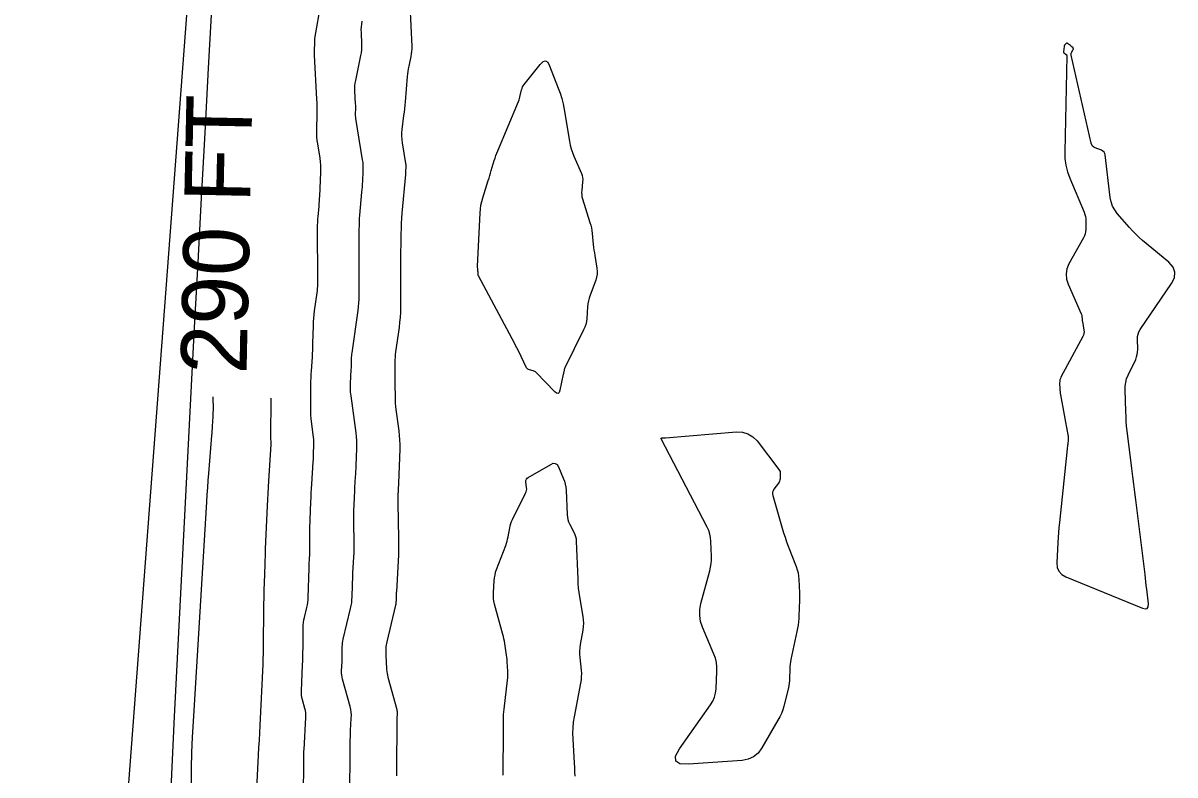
# Model space of a CAD drawing. Extents: x 1768942 to 1774819, y 723037 to 732099.
# Drawn here: x 1770524.3 to 1770629.2, y 730312.3 to 730380.8 of the extents above; entities that cross this region are included whole.
import ezdxf

# ---------------------------------------------------------------- set-up
doc = ezdxf.new("R2010")
doc.units = 0
for name, color, linetype in [('R_Contour Annot', 7, 'Continuous'), ('R_Contours', 7, 'Continuous'), ('R_Horz Alg', 7, 'Continuous')]:
    doc.layers.add(name, color=color, linetype=linetype)

msp = doc.modelspace()

# ---------------------------------------------------------------- linework, layer by layer
at = {"layer": 'R_Contours'}
for points in [[(1770549.81, 730309.86), (1770549.86, 730312.64), (1770549.86, 730312.8), (1770549.87, 730312.97), (1770549.87, 730313.14), (1770549.87, 730313.3), (1770549.87, 730313.97), (1770549.87, 730314.13), (1770549.88, 730314.3), (1770549.88, 730314.46), (1770549.89, 730314.63), (1770550.05, 730317.54), (1770550.05, 730317.75), (1770550.04, 730317.96), (1770550.01, 730318.16), (1770549.96, 730318.36), (1770549.75, 730319.16), (1770549.7, 730319.36), (1770549.67, 730319.56), (1770549.65, 730319.77), (1770549.65, 730319.97), (1770549.75, 730322.3), (1770549.77, 730322.69), (1770549.78, 730323.08), (1770549.79, 730323.47), (1770549.8, 730323.86), (1770549.81, 730325.73), (1770549.82, 730325.96), (1770549.84, 730326.2), (1770549.88, 730326.42), (1770549.93, 730326.65), (1770550.14, 730327.56), (1770550.19, 730327.79), (1770550.23, 730328.02), (1770550.25, 730328.25), (1770550.27, 730328.48), (1770550.34, 730331.15), (1770550.34, 730331.32), (1770550.35, 730331.49), (1770550.36, 730331.66), (1770550.37, 730331.83), (1770550.41, 730332.52), (1770550.41, 730332.69), (1770550.42, 730332.86), (1770550.42, 730333.03), (1770550.42, 730333.2), (1770550.4, 730333.97), (1770550.4, 730334.16), (1770550.4, 730334.34), (1770550.4, 730334.53), (1770550.41, 730334.71), (1770550.51, 730337.17), (1770550.53, 730337.57), (1770550.55, 730337.97), (1770550.58, 730338.38), (1770550.6, 730338.78), (1770550.73, 730340.83), (1770550.74, 730341.02), (1770550.75, 730341.21), (1770550.76, 730341.4), (1770550.76, 730341.58), (1770550.79, 730342.33), (1770550.79, 730342.52), (1770550.79, 730342.71), (1770550.77, 730342.9), (1770550.75, 730343.08), (1770550.57, 730344.48), (1770550.53, 730344.77), (1770550.51, 730345.07), (1770550.49, 730345.36), (1770550.49, 730345.66), (1770550.52, 730347.85), (1770550.52, 730348.17), (1770550.53, 730348.48), (1770550.55, 730348.79), (1770550.57, 730349.1), (1770550.65, 730350.35), (1770550.67, 730350.66), (1770550.68, 730350.98), (1770550.69, 730351.29), (1770550.7, 730351.6), (1770550.74, 730353.22), (1770550.75, 730353.56), (1770550.78, 730353.9), (1770550.81, 730354.24), (1770550.85, 730354.58), (1770551.08, 730356.22), (1770551.11, 730356.41), (1770551.12, 730356.61), (1770551.14, 730356.81), (1770551.14, 730357.01), (1770551.14, 730357.82), (1770551.14, 730358.02), (1770551.14, 730358.22), (1770551.14, 730358.42), (1770551.14, 730358.62), (1770551.12, 730360.94), (1770551.11, 730361.12), (1770551.11, 730361.3), (1770551.11, 730361.49), (1770551.12, 730361.67), (1770551.12, 730362.4), (1770551.13, 730362.58), (1770551.13, 730362.76), (1770551.14, 730362.94), (1770551.16, 730363.13), (1770551.25, 730364.12), (1770551.26, 730364.34), (1770551.28, 730364.57), (1770551.3, 730364.79), (1770551.31, 730365.02), (1770551.42, 730367.18), (1770551.43, 730367.5), (1770551.42, 730367.83), (1770551.39, 730368.15), (1770551.35, 730368.48), (1770551.14, 730369.77), (1770551.09, 730370.09), (1770551.06, 730370.42), (1770551.05, 730370.74), (1770551.05, 730371.07), (1770551.08, 730372.49), (1770551.09, 730372.83), (1770551.09, 730373.18), (1770551.08, 730373.52), (1770551.06, 730373.86), (1770550.83, 730377.86), (1770550.83, 730377.92), (1770550.83, 730377.98), (1770550.83, 730378.03), (1770550.83, 730378.09), (1770550.85, 730378.32), (1770550.85, 730378.38), (1770550.85, 730378.43), (1770550.85, 730378.48), (1770550.85, 730378.53), (1770550.86, 730378.75), (1770550.87, 730378.8), (1770550.87, 730378.85), (1770550.87, 730378.9), (1770550.87, 730378.95), (1770550.87, 730379.16), (1770550.87, 730379.22), (1770550.87, 730379.27), (1770550.87, 730379.32), (1770550.88, 730379.37), (1770552.03, 730385.95)], [(1770559.51, 730382.4), (1770559.69, 730378.66), (1770559.69, 730378.43), (1770559.68, 730378.2), (1770559.65, 730377.97), (1770559.61, 730377.74), (1770559.42, 730376.84), (1770559.38, 730376.61), (1770559.34, 730376.38), (1770559.31, 730376.15), (1770559.28, 730375.92), (1770559.08, 730373.61), (1770559.05, 730373.29), (1770559.02, 730372.98), (1770558.99, 730372.67), (1770558.95, 730372.35), (1770558.8, 730371.1), (1770558.77, 730370.79), (1770558.77, 730370.48), (1770558.79, 730370.17), (1770558.82, 730369.86), (1770559.13, 730367.99), (1770559.14, 730367.9), (1770559.15, 730367.82), (1770559.15, 730367.74), (1770559.15, 730367.66), (1770559.13, 730367.32), (1770559.13, 730367.24), (1770559.12, 730367.16), (1770559.11, 730367.07), (1770559.11, 730366.99), (1770558.8, 730363.46), (1770558.76, 730363), (1770558.73, 730362.53), (1770558.72, 730362.06), (1770558.71, 730361.6), (1770558.68, 730358.96), (1770558.68, 730358.88), (1770558.68, 730358.79), (1770558.68, 730358.7), (1770558.68, 730358.61), (1770558.68, 730358.26), (1770558.68, 730358.17), (1770558.68, 730358.08), (1770558.68, 730357.99), (1770558.68, 730357.9), (1770558.67, 730354.9), (1770558.66, 730354.44), (1770558.63, 730353.98), (1770558.59, 730353.53), (1770558.54, 730353.07), (1770558.22, 730350.84), (1770558.19, 730350.59), (1770558.17, 730350.35), (1770558.16, 730350.1), (1770558.15, 730349.86), (1770558.15, 730348.87), (1770558.15, 730348.62), (1770558.15, 730348.38), (1770558.15, 730348.13), (1770558.15, 730347.88), (1770558.17, 730346.7), (1770558.18, 730346.42), (1770558.19, 730346.15), (1770558.22, 730345.87), (1770558.25, 730345.59), (1770558.51, 730343.64), (1770558.56, 730343.23), (1770558.59, 730342.81), (1770558.6, 730342.39), (1770558.6, 730341.97), (1770558.49, 730338.88), (1770558.48, 730338.79), (1770558.48, 730338.71), (1770558.48, 730338.62), (1770558.47, 730338.53), (1770558.45, 730338.19), (1770558.44, 730338.11), (1770558.44, 730338.02), (1770558.43, 730337.94), (1770558.43, 730337.85), (1770558.41, 730337.45), (1770558.41, 730337.35), (1770558.41, 730337.26), (1770558.41, 730337.16), (1770558.41, 730337.07), (1770558.49, 730333.85), (1770558.49, 730333.34), (1770558.49, 730332.84), (1770558.48, 730332.33), (1770558.45, 730331.82), (1770558.29, 730328.98), (1770558.28, 730328.88), (1770558.28, 730328.78), (1770558.27, 730328.68), (1770558.27, 730328.58), (1770558.26, 730328.17), (1770558.25, 730328.07), (1770558.24, 730327.97), (1770558.23, 730327.87), (1770558.21, 730327.77), (1770557.41, 730324.43), (1770557.38, 730324.29), (1770557.35, 730324.14), (1770557.34, 730324), (1770557.34, 730323.85), (1770557.34, 730323.26), (1770557.34, 730323.11), (1770557.34, 730322.97), (1770557.35, 730322.82), (1770557.36, 730322.67), (1770557.4, 730321.9), (1770557.41, 730321.73), (1770557.44, 730321.55), (1770557.47, 730321.38), (1770557.51, 730321.21), (1770558.32, 730318.26), (1770558.34, 730318.17), (1770558.36, 730318.07), (1770558.36, 730317.97), (1770558.36, 730317.87), (1770558.34, 730317.48), (1770558.33, 730317.38), (1770558.33, 730317.28), (1770558.33, 730317.19), (1770558.33, 730317.09), (1770558.3, 730312.93), (1770558.3, 730312.84), (1770558.3, 730312.75), (1770558.3, 730312.66), (1770558.3, 730312.57), (1770558.29, 730312.21)], [(1770554.06, 730311.32), (1770554.07, 730312.35), (1770554.08, 730312.6), (1770554.08, 730312.86), (1770554.09, 730313.12), (1770554.09, 730313.37), (1770554.1, 730315.24), (1770554.1, 730315.51), (1770554.11, 730315.79), (1770554.12, 730316.07), (1770554.13, 730316.35), (1770554.19, 730317.46), (1770554.2, 730317.74), (1770554.18, 730318.01), (1770554.14, 730318.28), (1770554.08, 730318.55), (1770553.4, 730321.02), (1770553.36, 730321.21), (1770553.33, 730321.4), (1770553.31, 730321.59), (1770553.31, 730321.78), (1770553.35, 730322.61), (1770553.36, 730322.78), (1770553.36, 730322.95), (1770553.36, 730323.13), (1770553.37, 730323.3), (1770553.37, 730323.99), (1770553.38, 730324.16), (1770553.4, 730324.33), (1770553.42, 730324.5), (1770553.46, 730324.67), (1770554.13, 730327.47), (1770554.18, 730327.73), (1770554.23, 730327.99), (1770554.25, 730328.26), (1770554.27, 730328.53), (1770554.3, 730329.6), (1770554.31, 730329.87), (1770554.32, 730330.14), (1770554.33, 730330.41), (1770554.34, 730330.67), (1770554.43, 730332.17), (1770554.45, 730332.51), (1770554.45, 730332.85), (1770554.46, 730333.19), (1770554.45, 730333.52), (1770554.41, 730335.25), (1770554.41, 730335.53), (1770554.41, 730335.8), (1770554.41, 730336.07), (1770554.42, 730336.35), (1770554.47, 730337.51), (1770554.48, 730337.75), (1770554.5, 730338), (1770554.51, 730338.24), (1770554.52, 730338.49), (1770554.58, 730339.47), (1770554.6, 730339.71), (1770554.61, 730339.96), (1770554.62, 730340.2), (1770554.63, 730340.45), (1770554.69, 730342.06), (1770554.7, 730342.41), (1770554.69, 730342.76), (1770554.66, 730343.11), (1770554.62, 730343.45), (1770554.17, 730346.84), (1770554.15, 730347), (1770554.13, 730347.16), (1770554.13, 730347.32), (1770554.13, 730347.48), (1770554.13, 730348.2), (1770554.14, 730348.32), (1770554.14, 730348.44), (1770554.15, 730348.56), (1770554.15, 730348.67), (1770554.18, 730349.14), (1770554.19, 730349.26), (1770554.2, 730349.38), (1770554.2, 730349.5), (1770554.2, 730349.62), (1770554.22, 730350.21), (1770554.22, 730350.34), (1770554.23, 730350.48), (1770554.25, 730350.62), (1770554.26, 730350.75), (1770554.8, 730354.59), (1770554.85, 730354.94), (1770554.88, 730355.3), (1770554.9, 730355.65), (1770554.9, 730356.01), (1770554.91, 730357.68), (1770554.91, 730357.91), (1770554.91, 730358.15), (1770554.91, 730358.39), (1770554.91, 730358.62), (1770554.9, 730359.57), (1770554.9, 730359.81), (1770554.9, 730360.05), (1770554.9, 730360.28), (1770554.9, 730360.52), (1770554.91, 730362), (1770554.92, 730362.32), (1770554.93, 730362.65), (1770554.95, 730362.97), (1770554.98, 730363.3), (1770555.16, 730365.37), (1770555.18, 730365.62), (1770555.2, 730365.86), (1770555.22, 730366.11), (1770555.23, 730366.35), (1770555.28, 730367.33), (1770555.28, 730367.58), (1770555.28, 730367.82), (1770555.26, 730368.07), (1770555.22, 730368.31), (1770554.61, 730372.1), (1770554.59, 730372.21), (1770554.58, 730372.32), (1770554.58, 730372.43), (1770554.58, 730372.54), (1770554.59, 730372.98), (1770554.59, 730373.09), (1770554.59, 730373.2), (1770554.59, 730373.31), (1770554.58, 730373.42), (1770554.51, 730374.61), (1770554.51, 730374.84), (1770554.52, 730375.07), (1770554.54, 730375.31), (1770554.59, 730375.54), (1770555.07, 730377.83), (1770555.12, 730378.08), (1770555.15, 730378.34), (1770555.16, 730378.6), (1770555.16, 730378.86), (1770555.11, 730379.91), (1770555.1, 730380.17), (1770555.11, 730380.43), (1770555.14, 730380.69), (1770555.17, 730380.95)], [(1770539.64, 730311.5), (1770539.65, 730312.92), (1770539.68, 730314.34), (1770539.74, 730315.76), (1770539.81, 730317.18), (1770541.04, 730337.18), (1770541.08, 730337.83), (1770541.12, 730338.48), (1770541.17, 730339.12), (1770541.22, 730339.77), (1770541.49, 730343.23), (1770541.51, 730343.44), (1770541.52, 730343.65), (1770541.54, 730343.86), (1770541.55, 730344.07), (1770541.61, 730344.91), (1770541.62, 730345.11), (1770541.62, 730345.32), (1770541.63, 730345.53), (1770541.63, 730345.74), (1770541.61, 730346.57), (1770541.61, 730346.74)], [(1770545.59, 730311.03), (1770545.75, 730314.11), (1770545.78, 730314.79), (1770545.82, 730315.46), (1770545.85, 730316.14), (1770545.89, 730316.81), (1770546.16, 730322.39), (1770546.17, 730322.51), (1770546.17, 730322.63), (1770546.18, 730322.75), (1770546.18, 730322.87), (1770546.19, 730323.35), (1770546.19, 730323.47), (1770546.2, 730323.59), (1770546.2, 730323.71), (1770546.2, 730323.83), (1770546.24, 730327.7), (1770546.24, 730328), (1770546.25, 730328.29), (1770546.26, 730328.58), (1770546.26, 730328.88), (1770546.3, 730330.08), (1770546.31, 730330.36), (1770546.32, 730330.63), (1770546.33, 730330.91), (1770546.34, 730331.19), (1770546.38, 730332.84), (1770546.38, 730332.85), (1770546.38, 730332.87), (1770546.38, 730332.89), (1770546.38, 730332.89), (1770546.56, 730336.82), (1770546.58, 730337.39), (1770546.61, 730337.95), (1770546.64, 730338.51), (1770546.68, 730339.08), (1770546.88, 730342.41), (1770546.88, 730342.44), (1770546.88, 730342.46), (1770546.89, 730342.49), (1770546.89, 730342.51), (1770546.89, 730342.61), (1770546.89, 730342.64), (1770546.89, 730342.66), (1770546.89, 730342.69), (1770546.89, 730342.71), (1770546.86, 730342.9), (1770546.86, 730342.93), (1770546.85, 730342.97), (1770546.85, 730343.01), (1770546.85, 730343.05), (1770546.89, 730346.62)], [(1770568, 730312.28), (1770568, 730312.61), (1770568, 730312.93), (1770568, 730313.26), (1770568.05, 730315.4), (1770568.05, 730315.64), (1770568.05, 730315.88), (1770568.05, 730316.13), (1770568.05, 730316.37), (1770568.04, 730317.33), (1770568.04, 730317.57), (1770568.04, 730317.82), (1770568.06, 730318.06), (1770568.09, 730318.3), (1770568.4, 730320.93), (1770568.43, 730321.14), (1770568.44, 730321.35), (1770568.44, 730321.56), (1770568.43, 730321.77), (1770568.38, 730322.6), (1770568.37, 730322.81), (1770568.35, 730323.02), (1770568.32, 730323.22), (1770568.29, 730323.43), (1770568.16, 730324.28), (1770568.12, 730324.49), (1770568.08, 730324.7), (1770568.03, 730324.91), (1770567.98, 730325.11), (1770567.23, 730327.86), (1770567.17, 730328.12), (1770567.13, 730328.38), (1770567.12, 730328.64), (1770567.13, 730328.91), (1770567.19, 730329.98), (1770567.22, 730330.25), (1770567.27, 730330.51), (1770567.33, 730330.77), (1770567.42, 730331.02), (1770568.25, 730333.21), (1770568.31, 730333.4), (1770568.37, 730333.59), (1770568.42, 730333.79), (1770568.46, 730333.99), (1770568.61, 730334.8), (1770568.65, 730335), (1770568.71, 730335.19), (1770568.78, 730335.38), (1770568.86, 730335.57), (1770570.06, 730337.96), (1770570.11, 730338.08), (1770570.14, 730338.21), (1770570.16, 730338.34), (1770570.15, 730338.47), (1770570.09, 730339), (1770570.09, 730339.13), (1770570.13, 730339.23), (1770570.19, 730339.33), (1770570.29, 730339.4), (1770572.34, 730340.59), (1770572.57, 730340.69), (1770572.76, 730340.68), (1770572.92, 730340.57), (1770573.05, 730340.36), (1770573.49, 730339.32), (1770573.59, 730339.06), (1770573.66, 730338.79), (1770573.71, 730338.51), (1770573.74, 730338.23), (1770573.84, 730335.99), (1770573.86, 730335.77), (1770573.9, 730335.57), (1770573.97, 730335.37), (1770574.06, 730335.17), (1770574.45, 730334.41), (1770574.54, 730334.21), (1770574.61, 730334.01), (1770574.65, 730333.81), (1770574.67, 730333.59), (1770574.8, 730330.14), (1770574.82, 730329.73), (1770574.85, 730329.33), (1770574.9, 730328.93), (1770574.96, 730328.52), (1770575.27, 730326.75), (1770575.31, 730326.44), (1770575.32, 730326.12), (1770575.31, 730325.81), (1770575.27, 730325.49), (1770575.03, 730324.18), (1770574.99, 730323.89), (1770574.96, 730323.59), (1770574.96, 730323.3), (1770574.98, 730323.01), (1770575.11, 730321.84), (1770575.13, 730321.55), (1770575.12, 730321.25), (1770575.1, 730320.96), (1770575.06, 730320.67), (1770574.47, 730317.6), (1770574.4, 730317.1), (1770574.35, 730316.6), (1770574.33, 730316.1), (1770574.35, 730315.6), (1770574.49, 730313.38), (1770574.51, 730312.98), (1770574.52, 730312.58), (1770574.53, 730312.18)]]:
    msp.add_lwpolyline(points, dxfattribs=at)
for points in [[(1770623.68, 730363.76), (1770623.49, 730364.11), (1770623.35, 730364.49), (1770623.27, 730364.9), (1770622.81, 730368.77), (1770622.78, 730368.91), (1770622.71, 730369.03), (1770622.61, 730369.12), (1770622.48, 730369.19), (1770621.9, 730369.42), (1770621.77, 730369.48), (1770621.66, 730369.58), (1770621.59, 730369.69), (1770621.54, 730369.83), (1770619.72, 730377.85), (1770619.71, 730377.91), (1770619.71, 730377.97), (1770619.72, 730378.04), (1770619.75, 730378.09), (1770619.9, 730378.37), (1770619.92, 730378.41), (1770619.92, 730378.44), (1770619.91, 730378.47), (1770619.89, 730378.51), (1770619.77, 730378.63), (1770619.74, 730378.66), (1770619.71, 730378.69), (1770619.68, 730378.71), (1770619.65, 730378.74), (1770619.37, 730378.93), (1770619.34, 730378.95), (1770619.31, 730378.95), (1770619.28, 730378.95), (1770619.25, 730378.92), (1770619.14, 730378.8), (1770619.12, 730378.77), (1770619.1, 730378.74), (1770619.09, 730378.7), (1770619.08, 730378.66), (1770619.03, 730378.16), (1770619.03, 730378.12), (1770619.04, 730378.08), (1770619.06, 730378.05), (1770619.1, 730378.03), (1770619.25, 730377.93), (1770619.28, 730377.91), (1770619.3, 730377.87), (1770619.32, 730377.84), (1770619.32, 730377.8), (1770619.13, 730369.06), (1770619.15, 730368.44), (1770619.23, 730367.83), (1770619.38, 730367.24), (1770619.59, 730366.65), (1770620.89, 730363.55), (1770620.96, 730363.36), (1770621.01, 730363.17), (1770621.04, 730362.98), (1770621.04, 730362.78), (1770621.04, 730361.98), (1770621.03, 730361.78), (1770620.99, 730361.59), (1770620.93, 730361.4), (1770620.84, 730361.22), (1770619.52, 730358.85), (1770619.33, 730358.39), (1770619.25, 730357.94), (1770619.29, 730357.47), (1770619.44, 730357.01), (1770620.64, 730354.29), (1770620.66, 730354.24), (1770620.68, 730354.18), (1770620.69, 730354.13), (1770620.7, 730354.07), (1770620.71, 730353.84), (1770620.72, 730353.78), (1770620.72, 730353.72), (1770620.73, 730353.66), (1770620.74, 730353.61), (1770620.88, 730352.81), (1770620.89, 730352.66), (1770620.88, 730352.51), (1770620.85, 730352.37), (1770620.79, 730352.23), (1770618.79, 730348.53), (1770618.74, 730348.41), (1770618.7, 730348.28), (1770618.68, 730348.15), (1770618.67, 730348.02), (1770618.69, 730347.47), (1770618.7, 730347.34), (1770618.71, 730347.2), (1770618.73, 730347.07), (1770618.75, 730346.93), (1770619.42, 730343.29), (1770619.44, 730343.19), (1770619.45, 730343.08), (1770619.45, 730342.97), (1770619.44, 730342.87), (1770619.4, 730342.44), (1770619.39, 730342.33), (1770619.37, 730342.22), (1770619.36, 730342.11), (1770619.35, 730342.01), (1770618.65, 730335.29), (1770618.6, 730334.83), (1770618.57, 730334.38), (1770618.53, 730333.92), (1770618.51, 730333.46), (1770618.42, 730331.62), (1770618.45, 730331.2), (1770618.6, 730330.85), (1770618.86, 730330.57), (1770619.22, 730330.36), (1770626.21, 730327.49), (1770626.47, 730327.42), (1770626.65, 730327.47), (1770626.74, 730327.63), (1770626.75, 730327.9), (1770626.6, 730329.22), (1770626.56, 730329.55), (1770626.52, 730329.88), (1770626.48, 730330.22), (1770626.44, 730330.55), (1770625.61, 730337.35), (1770625.52, 730338.07), (1770625.43, 730338.79), (1770625.34, 730339.5), (1770625.25, 730340.22), (1770624.82, 730343.64), (1770624.77, 730344.08), (1770624.74, 730344.53), (1770624.71, 730344.97), (1770624.69, 730345.41), (1770624.62, 730347.38), (1770624.63, 730347.72), (1770624.68, 730348.06), (1770624.77, 730348.38), (1770624.9, 730348.7), (1770625.59, 730350.15), (1770625.68, 730350.37), (1770625.74, 730350.59), (1770625.77, 730350.82), (1770625.78, 730351.06), (1770625.75, 730352), (1770625.76, 730352.24), (1770625.81, 730352.46), (1770625.89, 730352.67), (1770626, 730352.87), (1770628.86, 730357.06), (1770629.12, 730357.59), (1770629.17, 730358.09), (1770628.99, 730358.56), (1770628.6, 730358.99), (1770626.21, 730360.99), (1770625.9, 730361.26), (1770625.59, 730361.55), (1770625.3, 730361.85), (1770625.02, 730362.16), (1770623.92, 730363.43)], [(1770575.21, 730366.9), (1770575.25, 730366.71), (1770575.26, 730366.52), (1770575.25, 730366.33), (1770575.16, 730365.54), (1770575.15, 730365.35), (1770575.16, 730365.15), (1770575.18, 730364.96), (1770575.23, 730364.77), (1770575.91, 730362.62), (1770575.98, 730362.37), (1770576.04, 730362.13), (1770576.08, 730361.88), (1770576.11, 730361.62), (1770576.22, 730360.61), (1770576.25, 730360.35), (1770576.28, 730360.1), (1770576.32, 730359.85), (1770576.36, 730359.6), (1770576.55, 730358.45), (1770576.57, 730358.17), (1770576.57, 730357.9), (1770576.52, 730357.64), (1770576.44, 730357.37), (1770575.93, 730355.99), (1770575.85, 730355.74), (1770575.78, 730355.48), (1770575.73, 730355.21), (1770575.7, 730354.95), (1770575.62, 730353.87), (1770575.59, 730353.6), (1770575.53, 730353.34), (1770575.44, 730353.09), (1770575.34, 730352.84), (1770573.63, 730349.38), (1770573.61, 730349.33), (1770573.59, 730349.29), (1770573.58, 730349.24), (1770573.57, 730349.19), (1770573.53, 730348.99), (1770573.52, 730348.94), (1770573.51, 730348.89), (1770573.5, 730348.84), (1770573.49, 730348.79), (1770573.18, 730347.34), (1770573.11, 730347.14), (1770573.01, 730347.04), (1770572.87, 730347.07), (1770572.71, 730347.2), (1770571.02, 730348.96), (1770570.96, 730349.01), (1770570.89, 730349.06), (1770570.81, 730349.09), (1770570.73, 730349.12), (1770570.4, 730349.2), (1770570.32, 730349.22), (1770570.25, 730349.26), (1770570.2, 730349.32), (1770570.15, 730349.39), (1770569.4, 730350.92), (1770569.26, 730351.2), (1770569.11, 730351.48), (1770568.97, 730351.75), (1770568.82, 730352.03), (1770565.77, 730357.76), (1770565.75, 730357.8), (1770565.74, 730357.84), (1770565.73, 730357.88), (1770565.73, 730357.92), (1770565.73, 730358.08), (1770565.73, 730358.13), (1770565.72, 730358.17), (1770565.72, 730358.21), (1770565.72, 730358.25), (1770565.7, 730358.44), (1770565.69, 730358.48), (1770565.69, 730358.53), (1770565.69, 730358.57), (1770565.69, 730358.62), (1770565.91, 730363.49), (1770565.94, 730363.84), (1770565.99, 730364.19), (1770566.06, 730364.53), (1770566.16, 730364.87), (1770566.66, 730366.43), (1770566.73, 730366.66), (1770566.8, 730366.89), (1770566.87, 730367.12), (1770566.93, 730367.34), (1770567.2, 730368.26), (1770567.27, 730368.48), (1770567.35, 730368.71), (1770567.43, 730368.93), (1770567.52, 730369.15), (1770569.41, 730373.65), (1770569.46, 730373.78), (1770569.5, 730373.91), (1770569.54, 730374.04), (1770569.57, 730374.17), (1770569.69, 730374.7), (1770569.73, 730374.83), (1770569.78, 730374.96), (1770569.84, 730375.07), (1770569.92, 730375.18), (1770571.38, 730377.02), (1770571.64, 730377.27), (1770571.87, 730377.33), (1770572.07, 730377.21), (1770572.24, 730376.89), (1770573.03, 730374.86), (1770573.2, 730374.39), (1770573.34, 730373.9), (1770573.47, 730373.41), (1770573.56, 730372.91), (1770574.04, 730370.01), (1770574.11, 730369.66), (1770574.2, 730369.33), (1770574.31, 730368.99), (1770574.44, 730368.66), (1770575.14, 730367.08)], [(1770593.18, 730340.03), (1770593.22, 730339.93), (1770593.24, 730339.83), (1770593.24, 730339.72), (1770593.22, 730339.28), (1770593.21, 730339.17), (1770593.18, 730339.07), (1770593.13, 730338.97), (1770593.07, 730338.88), (1770592.65, 730338.32), (1770592.58, 730338.19), (1770592.53, 730338.06), (1770592.53, 730337.92), (1770592.55, 730337.77), (1770593.42, 730334.79), (1770593.54, 730334.37), (1770593.68, 730333.96), (1770593.82, 730333.55), (1770593.97, 730333.15), (1770594.69, 730331.29), (1770594.79, 730331), (1770594.86, 730330.71), (1770594.91, 730330.42), (1770594.93, 730330.12), (1770594.98, 730328.88), (1770594.98, 730328.59), (1770594.99, 730328.3), (1770594.98, 730328), (1770594.97, 730327.71), (1770594.92, 730326.54), (1770594.9, 730326.25), (1770594.86, 730325.96), (1770594.82, 730325.67), (1770594.76, 730325.38), (1770594.21, 730322.81), (1770594.17, 730322.6), (1770594.14, 730322.38), (1770594.12, 730322.17), (1770594.11, 730321.95), (1770594.09, 730321.08), (1770594.08, 730320.87), (1770594.06, 730320.65), (1770594.03, 730320.44), (1770593.98, 730320.23), (1770593.56, 730318.58), (1770593.46, 730318.24), (1770593.34, 730317.91), (1770593.19, 730317.59), (1770593.02, 730317.28), (1770591.57, 730314.76), (1770591.23, 730314.3), (1770590.81, 730313.96), (1770590.32, 730313.73), (1770589.76, 730313.63), (1770584.87, 730313.28), (1770584.11, 730313.31), (1770583.72, 730313.56), (1770583.71, 730314.02), (1770584.07, 730314.69), (1770586.9, 730318.69), (1770587.1, 730319.03), (1770587.25, 730319.38), (1770587.35, 730319.76), (1770587.4, 730320.15), (1770587.47, 730321.77), (1770587.47, 730322.16), (1770587.42, 730322.56), (1770587.33, 730322.94), (1770587.19, 730323.31), (1770586.17, 730325.75), (1770585.99, 730326.28), (1770585.91, 730326.82), (1770585.92, 730327.36), (1770586.02, 730327.91), (1770586.82, 730330.89), (1770586.9, 730331.22), (1770586.95, 730331.55), (1770586.98, 730331.88), (1770586.98, 730332.22), (1770586.93, 730333.58), (1770586.9, 730333.92), (1770586.83, 730334.24), (1770586.73, 730334.56), (1770586.59, 730334.86), (1770582.4, 730342.92), (1770582.39, 730342.95), (1770582.39, 730342.98), (1770582.41, 730342.99), (1770582.45, 730343), (1770582.62, 730343.01), (1770582.67, 730343.01), (1770582.71, 730343.01), (1770582.75, 730343.02), (1770582.8, 730343.02), (1770589.25, 730343.54), (1770589.8, 730343.53), (1770590.3, 730343.38), (1770590.74, 730343.11), (1770591.12, 730342.72), (1770593.12, 730340.12)]]:
    msp.add_lwpolyline(points, close=True, dxfattribs=at)
at = {"layer": 'R_Horz Alg'}
msp.add_line((1770527.75, 730229.26), (1770556.18, 730606.87), dxfattribs=at)
msp.add_arc((1781982.99, 729746.52), 11459.16, 175.694205, 179.479591, dxfattribs=at)

# ---------------------------------------------------------------- texts
at = {"layer": 'R_Contour Annot'}
msp.add_text('290 FT', height=6, rotation=88.7958, dxfattribs=at).set_placement((1770544.65, 730348.77))

doc.saveas('drawing.dxf')
